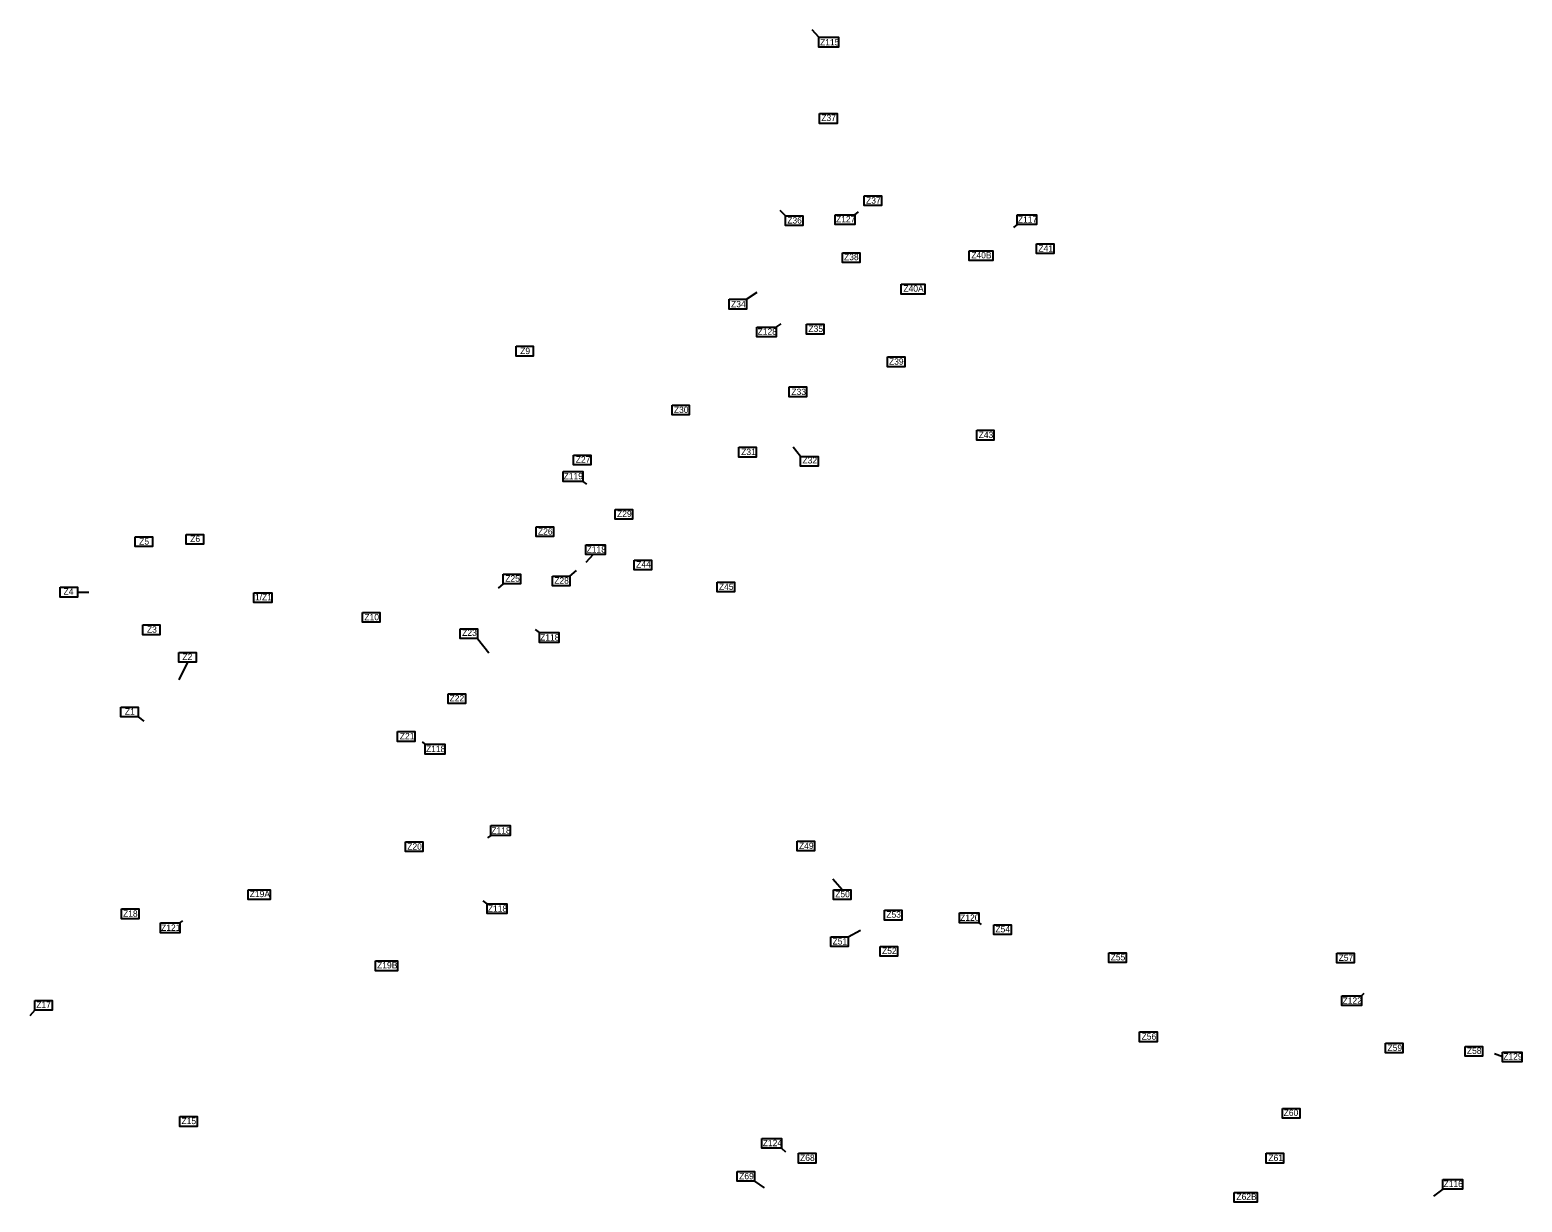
# Model space of a CAD drawing. Extents: x -443485 to -434416, y -1135265 to -1129797.
# Drawn here: x -443022 to -440666, y -1131648 to -1129797 of the extents above; entities that cross this region are included whole.
import ezdxf

# ---------------------------------------------------------------- set-up
doc = ezdxf.new("R2010")
doc.units = 0
doc.layers.add('Vrstva 3', color=7, linetype='Continuous')
doc.layers.add('Vrstva 8', color=7, linetype='Continuous')

msp = doc.modelspace()

# ---------------------------------------------------------------- linework, layer by layer
at = {"layer": 'Vrstva 3'}
for p, q in [((-441776.5, -1129808.4), (-441787.2, -1129796.7)), ((-441829.1, -1130090.3), (-441838, -1130081.7)), ((-441805.4, -1130470.4), (-441817.3, -1130455.4)), ((-442169.8, -1130659.1), (-442159.4, -1130650.4)), ((-442275.3, -1130671.3), (-442283.1, -1130678.3)), ((-442947.3, -1130684.5), (-442929.2, -1130684.8)), ((-442315.6, -1130757.6), (-442297.5, -1130780.5)), ((-442773.4, -1130795.3), (-442787.4, -1130823.1)), ((-442851.5, -1130881.4), (-442842.3, -1130888.4)), ((-441740.1, -1131154.3), (-441754.6, -1131137.8)), ((-441730.2, -1131228.8), (-441711, -1131218.2)), ((-443014.7, -1131344.8), (-443022.4, -1131353.5)), ((-441878.2, -1131614.7), (-441862.9, -1131625)), ((-440791.4, -1131627.3), (-440806.3, -1131638.4))]:
    msp.add_line(p, q, dxfattribs=at)
for points in [[(-441776.5, -1129808.4), (-441745.7, -1129808.4), (-441745.7, -1129823.8), (-441776.5, -1129823.8)], [(-441775.4, -1129929), (-441748, -1129929), (-441748, -1129944.4), (-441775.4, -1129944.4)], [(-441705.1, -1130058.7), (-441677.7, -1130058.7), (-441677.7, -1130074.1), (-441705.1, -1130074.1)], [(-441829.1, -1130090.3), (-441801.8, -1130090.3), (-441801.8, -1130105.7), (-441829.1, -1130105.7)], [(-441433.1, -1130134.4), (-441405.7, -1130134.4), (-441405.7, -1130149.8), (-441433.1, -1130149.8)], [(-441739.6, -1130148.5), (-441712.2, -1130148.5), (-441712.2, -1130163.9), (-441739.6, -1130163.9)], [(-441539.4, -1130145.7), (-441501.8, -1130145.7), (-441501.8, -1130161.1), (-441539.4, -1130161.1)], [(-441646.5, -1130198.4), (-441609.2, -1130198.4), (-441609.2, -1130213.8), (-441646.5, -1130213.8)], [(-441918.2, -1130222.1), (-441890.9, -1130222.1), (-441890.9, -1130237.5), (-441918.2, -1130237.5)], [(-441796.3, -1130261.6), (-441768.9, -1130261.6), (-441768.9, -1130277), (-441796.3, -1130277)], [(-442254.8, -1130296.3), (-442227.5, -1130296.3), (-442227.5, -1130311.7), (-442254.8, -1130311.7)], [(-441668.4, -1130313.2), (-441641, -1130313.2), (-441641, -1130328.6), (-441668.4, -1130328.6)], [(-441823.7, -1130360.6), (-441796.4, -1130360.6), (-441796.4, -1130376), (-441823.7, -1130376)], [(-442008.5, -1130389.3), (-441981.2, -1130389.3), (-441981.2, -1130404.7), (-442008.5, -1130404.7)], [(-441527.5, -1130428.9), (-441500.2, -1130428.9), (-441500.2, -1130444.3), (-441527.5, -1130444.3)], [(-441903, -1130455.8), (-441875.6, -1130455.8), (-441875.6, -1130471.2), (-441903, -1130471.2)], [(-442163.9, -1130468.1), (-442136.5, -1130468.1), (-442136.5, -1130483.5), (-442163.9, -1130483.5)], [(-441805.4, -1130470.4), (-441778, -1130470.4), (-441778, -1130485.8), (-441805.4, -1130485.8)], [(-442098.4, -1130554.1), (-442071.1, -1130554.1), (-442071.1, -1130569.5), (-442098.4, -1130569.5)], [(-442222.8, -1130581.2), (-442195.5, -1130581.2), (-442195.5, -1130596.5), (-442222.8, -1130596.5)], [(-442856.3, -1130597.4), (-442828.9, -1130597.4), (-442828.9, -1130612.7), (-442856.3, -1130612.7)], [(-442775.7, -1130593.4), (-442748.3, -1130593.4), (-442748.3, -1130608.8), (-442775.7, -1130608.8)], [(-442068.4, -1130633.9), (-442041.1, -1130633.9), (-442041.1, -1130649.3), (-442068.4, -1130649.3)], [(-442275.3, -1130655.9), (-442247.9, -1130655.9), (-442247.9, -1130671.3), (-442275.3, -1130671.3)], [(-442197.1, -1130659.1), (-442169.8, -1130659.1), (-442169.8, -1130674.5), (-442197.1, -1130674.5)], [(-441937.3, -1130668.5), (-441909.9, -1130668.5), (-441909.9, -1130683.9), (-441937.3, -1130683.9)], [(-442974.7, -1130676.8), (-442947.3, -1130676.8), (-442947.3, -1130692.2), (-442974.7, -1130692.2)], [(-442668.8, -1130685.4), (-442640.3, -1130685.4), (-442640.3, -1130700.8), (-442668.8, -1130700.8)], [(-442497.1, -1130716.5), (-442469.7, -1130716.5), (-442469.7, -1130731.9), (-442497.1, -1130731.9)], [(-442844.2, -1130736.3), (-442816.9, -1130736.3), (-442816.9, -1130751.7), (-442844.2, -1130751.7)], [(-442343, -1130742.2), (-442315.6, -1130742.2), (-442315.6, -1130757.6), (-442343, -1130757.6)], [(-442787.1, -1130779.9), (-442759.7, -1130779.9), (-442759.7, -1130795.3), (-442787.1, -1130795.3)], [(-442362, -1130845), (-442334.6, -1130845), (-442334.6, -1130860.4), (-442362, -1130860.4)], [(-442878.9, -1130866.1), (-442851.5, -1130866.1), (-442851.5, -1130881.4), (-442878.9, -1130881.4)], [(-442441.8, -1130904.7), (-442414.5, -1130904.7), (-442414.5, -1130920.1), (-442441.8, -1130920.1)], [(-442429.5, -1131078.6), (-442402.1, -1131078.6), (-442402.1, -1131094), (-442429.5, -1131094)], [(-441810.9, -1131077.7), (-441783.5, -1131077.7), (-441783.5, -1131093.1), (-441810.9, -1131093.1)], [(-442677.7, -1131154.6), (-442643.2, -1131154.6), (-442643.2, -1131170), (-442677.7, -1131170)], [(-441753.8, -1131154.3), (-441726.4, -1131154.3), (-441726.4, -1131169.7), (-441753.8, -1131169.7)], [(-442877.9, -1131184.7), (-442850.5, -1131184.7), (-442850.5, -1131200.1), (-442877.9, -1131200.1)], [(-441673.2, -1131186.9), (-441645.8, -1131186.9), (-441645.8, -1131202.2), (-441673.2, -1131202.2)], [(-441500.6, -1131209.7), (-441473.3, -1131209.7), (-441473.3, -1131225.1), (-441500.6, -1131225.1)], [(-441757.5, -1131228.8), (-441730.2, -1131228.8), (-441730.2, -1131244.2), (-441757.5, -1131244.2)], [(-441679.9, -1131243.9), (-441652.6, -1131243.9), (-441652.6, -1131259.3), (-441679.9, -1131259.3)], [(-441319, -1131254), (-441291.6, -1131254), (-441291.6, -1131269.4), (-441319, -1131269.4)], [(-440958.8, -1131254.3), (-440931.4, -1131254.3), (-440931.4, -1131269.7), (-440958.8, -1131269.7)], [(-442476.8, -1131266.9), (-442441.8, -1131266.9), (-442441.8, -1131282.3), (-442476.8, -1131282.3)], [(-443014.7, -1131329.4), (-442987.3, -1131329.4), (-442987.3, -1131344.8), (-443014.7, -1131344.8)], [(-441270.2, -1131379), (-441242.8, -1131379), (-441242.8, -1131394.4), (-441270.2, -1131394.4)], [(-440882, -1131396.5), (-440854.6, -1131396.5), (-440854.6, -1131411.9), (-440882, -1131411.9)], [(-440756.3, -1131401.9), (-440728.9, -1131401.9), (-440728.9, -1131417.3), (-440756.3, -1131417.3)], [(-441044.5, -1131499.6), (-441017.1, -1131499.6), (-441017.1, -1131515), (-441044.5, -1131515)], [(-442785.3, -1131512.6), (-442758, -1131512.6), (-442758, -1131528), (-442785.3, -1131528)], [(-441808.9, -1131570.5), (-441781.5, -1131570.5), (-441781.5, -1131585.9), (-441808.9, -1131585.9)], [(-441070.7, -1131570.5), (-441043.3, -1131570.5), (-441043.3, -1131585.9), (-441070.7, -1131585.9)], [(-441905.5, -1131599.3), (-441878.2, -1131599.3), (-441878.2, -1131614.7), (-441905.5, -1131614.7)], [(-440791.4, -1131611.9), (-440760.7, -1131611.9), (-440760.7, -1131627.3), (-440791.4, -1131627.3)], [(-441120.8, -1131632.3), (-441084.4, -1131632.3), (-441084.4, -1131647.7), (-441120.8, -1131647.7)]]:
    msp.add_lwpolyline(points, close=True, dxfattribs=at)
at = {"layer": 'Vrstva 8'}
for p, q in [((-441720.1, -1130088.6), (-441714.3, -1130084)), ((-441463.6, -1130104.2), (-441469.4, -1130108.5)), ((-441890.9, -1130222.1), (-441874, -1130210.7)), ((-441844, -1130266.2), (-441836.1, -1130260.9)), ((-442149.3, -1130509.6), (-442143.6, -1130514.2)), ((-442132.8, -1130625.1), (-442144.7, -1130637.5)), ((-442217.8, -1130748.4), (-442224.2, -1130743.6)), ((-442398, -1130924.7), (-442402.3, -1130921.1)), ((-442294.8, -1131068.6), (-442299.8, -1131072.4)), ((-442300.3, -1131176.7), (-442306.7, -1131171.9)), ((-442785.3, -1131206.9), (-442780.8, -1131203.4)), ((-441523.9, -1131206.4), (-441520.2, -1131209.2)), ((-440920.2, -1131322), (-440915.5, -1131317.9)), ((-440697.5, -1131418.4), (-440709.9, -1131413.3)), ((-441835.8, -1131562.7), (-441829.5, -1131568.4))]:
    msp.add_line(p, q, dxfattribs=at)
for points in [[(-441750.9, -1130088.6), (-441720.1, -1130088.6), (-441720.1, -1130104), (-441750.9, -1130104)], [(-441463.6, -1130088.8), (-441432.8, -1130088.8), (-441432.8, -1130104.2), (-441463.6, -1130104.2)], [(-441463.6, -1130088.8), (-441432.8, -1130088.8), (-441432.8, -1130104.2), (-441463.6, -1130104.2)], [(-441874.8, -1130266.2), (-441844, -1130266.2), (-441844, -1130281.6), (-441874.8, -1130281.6)], [(-442180.1, -1130494.2), (-442149.3, -1130494.2), (-442149.3, -1130509.6), (-442180.1, -1130509.6)], [(-442144.8, -1130609.7), (-442114, -1130609.7), (-442114, -1130625.1), (-442144.8, -1130625.1)], [(-442217.8, -1130748.4), (-442187, -1130748.4), (-442187, -1130763.8), (-442217.8, -1130763.8)], [(-442398, -1130924.7), (-442367.2, -1130924.7), (-442367.2, -1130940.1), (-442398, -1130940.1)], [(-442294.8, -1131053.2), (-442264, -1131053.2), (-442264, -1131068.6), (-442294.8, -1131068.6)], [(-442300.3, -1131176.7), (-442269.5, -1131176.7), (-442269.5, -1131192.1), (-442300.3, -1131192.1)], [(-441554.7, -1131191), (-441523.9, -1131191), (-441523.9, -1131206.4), (-441554.7, -1131206.4)], [(-442816.1, -1131206.9), (-442785.3, -1131206.9), (-442785.3, -1131222.3), (-442816.1, -1131222.3)], [(-440951, -1131322), (-440920.2, -1131322), (-440920.2, -1131337.4), (-440951, -1131337.4)], [(-440697.5, -1131410.7), (-440666.8, -1131410.7), (-440666.8, -1131426.1), (-440697.5, -1131426.1)], [(-441866.6, -1131547.3), (-441835.8, -1131547.3), (-441835.8, -1131562.7), (-441866.6, -1131562.7)]]:
    msp.add_lwpolyline(points, close=True, dxfattribs=at)

# ---------------------------------------------------------------- texts
at = {"layer": 'Vrstva 3'}
for s, p in [('Z115', (-441774.7, -1129821.3)), ('Z37', (-441772.8, -1129940.6)), ('Z37', (-441702.1, -1130071)), ('Z36', (-441826.5, -1130102.5)), ('Z38', (-441736.9, -1130160.4)), ('Z40B', (-441536, -1130157.5)), ('Z41', (-441430, -1130146.8)), ('Z40A', (-441643.2, -1130210.2)), ('Z34', (-441915.3, -1130234.7)), ('Z35', (-441793.1, -1130273.7)), ('Z9', (-442248.2, -1130308.7)), ('Z39', (-441665.9, -1130325.4)), ('Z33', (-441820, -1130373.2)), ('Z30', (-442005.5, -1130401.6)), ('Z43', (-441524.3, -1130441.2)), ('Z31', (-441899.3, -1130468.1)), ('Z27', (-442160.4, -1130480.1)), ('Z32', (-441802.5, -1130481.3)), ('Z29', (-442095.2, -1130565.8)), ('Z5', (-442849.7, -1130609.4)), ('Z6', (-442769.2, -1130605.4)), ('Z26', (-442220.1, -1130593.6)), ('Z44', (-442065.1, -1130645.7)), ('Z25', (-442271.7, -1130668)), ('Z28', (-442194.4, -1130671.3)), ('Z45', (-441934.4, -1130681)), ('Z4', (-442969.1, -1130688.5)), ('1/Z1', (-442666.9, -1130697.4)), ('Z10', (-442494.1, -1130728.9)), ('Z3', (-442837.5, -1130748.5)), ('Z23', (-442339.8, -1130753.5)), ('Z2', (-442781.4, -1130791.5)), ('Z22', (-442359.7, -1130857.1)), ('Z1', (-442872.3, -1130878.1)), ('Z21', (-442438.2, -1130916.8)), ('Z20', (-442426.5, -1131091.1)), ('Z49', (-441808, -1131090)), ('Z19A', (-442675.2, -1131166.1)), ('Z50', (-441750.8, -1131166.3)), ('Z18', (-442875.2, -1131197.1)), ('Z53', (-441670.1, -1131198.5)), ('Z54', (-441497.9, -1131221.7)), ('Z51', (-441755, -1131240.9)), ('Z52', (-441676.9, -1131255.8)), ('Z55', (-441315.9, -1131266)), ('Z57', (-440956, -1131266.7)), ('Z19B', (-442474.1, -1131278.6)), ('Z17', (-443012.2, -1131341)), ('Z56', (-441267.1, -1131391.1)), ('Z59', (-440878.9, -1131409)), ('Z58', (-440753.5, -1131413.6)), ('Z15', (-442782.9, -1131524.5)), ('Z60', (-441042.8, -1131511.5)), ('Z68', (-441806.3, -1131582.6)), ('Z61', (-441066.9, -1131582.7)), ('Z69', (-441902.5, -1131611.6)), ('Z116', (-440790.4, -1131623.8)), ('Z62B', (-441117.4, -1131644.1))]:
    msp.add_text(s, height=10, dxfattribs=at).set_placement(p)
at = {"layer": 'Vrstva 8'}
for s, p in [('Z127', (-441749.5, -1130100.6)), ('Z117', (-441462.5, -1130101.2)), ('Z128', (-441873.4, -1130278.2)), ('Z119', (-442179.6, -1130506.2)), ('Z118', (-442143.3, -1130622)), ('Z118', (-442216.7, -1130760.9)), ('Z118', (-442396.9, -1130937.1)), ('Z118', (-442293.7, -1131065.7)), ('Z118', (-442299.3, -1131189.2)), ('Z120', (-441553.6, -1131203.5)), ('Z121', (-442815.1, -1131219.3)), ('Z122', (-440949.9, -1131334.5)), ('Z129', (-440696.1, -1131422.7)), ('Z124', (-441865.2, -1131559.3))]:
    msp.add_text(s, height=10, dxfattribs=at).set_placement(p)

doc.saveas('drawing.dxf')
